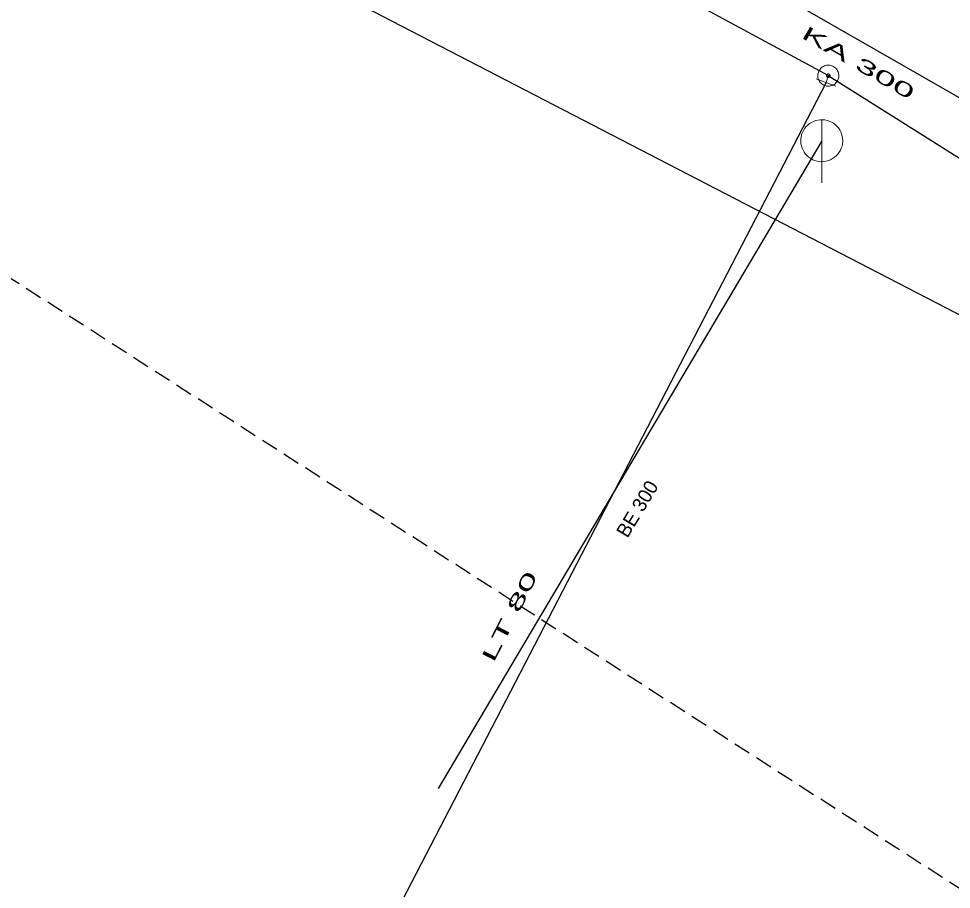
# Model space of a CAD drawing. Extents: x -687593 to -687108, y -975254 to -974717.
# Drawn here: x -687397.23 to -687352.84, y -974990.14 to -974948.69 of the extents above; entities that cross this region are included whole.
import ezdxf
from ezdxf.enums import TextEntityAlignment as Align

# ---------------------------------------------------------------- set-up
doc = ezdxf.new("R2010")
doc.units = 0
doc.header["$LTSCALE"] = 0.27
doc.linetypes.add('MEDIUM_DASHED', pattern=[4.5, 3, -1.5])
for name, color, linetype, lineweight in [('1', 7, 'Continuous', 25), ('14', 7, 'Continuous', 13), ('17', 7, 'Continuous', 25), ('22', 7, 'Continuous', 13), ('34', 7, 'Continuous', 13), ('47', 7, 'Continuous', 13), ('63', 7, 'MEDIUM_DASHED', 25)]:
    doc.layers.add(name, color=color, linetype=linetype, lineweight=lineweight)

msp = doc.modelspace()

# ---------------------------------------------------------------- linework, layer by layer
at = {"layer": '1'}
msp.add_lwpolyline([(-687190.553, -975166.941), (-687164.86, -975177.861), (-687155.924, -975158.837), (-687125.348, -975155.541), (-687124.826, -975139.621), (-687173.065, -975131.89), (-687231.828, -975028.025), (-687222.959, -975015.464), (-687237.898, -975004.026), (-687247.4, -975009.654), (-687276.892, -974983.781), (-687453.606, -974886.044), (-687460.232, -974860.45), (-687474.874, -974858.564), (-687482.889, -974882.272), (-687502.421, -974882.802), (-687499.452, -974907.164), (-687464.42, -974904.824), (-687331.319, -974973.728), (-687252.566, -975037.916), (-687192.379, -975151.48)], close=True, dxfattribs=at)
at = {"layer": '14', "lineweight": 25}
for p, q in [((-687339.967, -974959.63), (-687373.818, -974940.214)), ((-687359.013, -974954.503), (-687377.27, -974985.346))]:
    msp.add_line(p, q, dxfattribs=at)
at = {"layer": '14'}
msp.add_line((-687358.699, -974951.407), (-687358.806, -974951.731), dxfattribs=at)
at = {"layer": '17'}
for points in [[(-687358.699, -974951.407), (-687368.317, -974946.193), (-687385.348, -974936.838), (-687396.817, -974929.825)], [(-687358.699, -974951.407), (-687333.097, -974967.52), (-687321.645, -974974.737), (-687306.885, -974986.7), (-687303.706, -974988.972)], [(-687358.806, -974951.731), (-687385.932, -975004.085), (-687386.063, -975007.526), (-687384.796, -975013.772), (-687383.147, -975018.998), (-687376.673, -975029.833), (-687378.204, -975039.264)]]:
    msp.add_lwpolyline(points, dxfattribs=at)
at = {"layer": '22'}
msp.add_line((-687359.013, -974956.503), (-687359.012, -974953.503), dxfattribs=at)
msp.add_lwpolyline([(-687358.013, -974954.503), (-687358.018, -974954.394), (-687358.036, -974954.286), (-687358.066, -974954.18), (-687358.106, -974954.079), (-687358.158, -974953.982), (-687358.22, -974953.892), (-687358.292, -974953.809), (-687358.372, -974953.735), (-687358.46, -974953.669), (-687358.554, -974953.614), (-687358.654, -974953.569), (-687358.759, -974953.536), (-687358.866, -974953.514), (-687358.975, -974953.504), (-687359.085, -974953.506), (-687359.193, -974953.52), (-687359.3, -974953.545), (-687359.403, -974953.582), (-687359.501, -974953.631), (-687359.593, -974953.689), (-687359.679, -974953.758), (-687359.756, -974953.835), (-687359.825, -974953.921), (-687359.884, -974954.013), (-687359.932, -974954.111), (-687359.969, -974954.214), (-687359.995, -974954.321), (-687360.009, -974954.429), (-687360.012, -974954.539), (-687360.002, -974954.648), (-687359.981, -974954.755), (-687359.947, -974954.859), (-687359.903, -974954.959), (-687359.848, -974955.054), (-687359.782, -974955.142), (-687359.708, -974955.222), (-687359.625, -974955.294), (-687359.535, -974955.356), (-687359.439, -974955.408), (-687359.337, -974955.449), (-687359.232, -974955.479), (-687359.124, -974955.497), (-687359.014, -974955.503), (-687358.905, -974955.497), (-687358.797, -974955.479), (-687358.692, -974955.45), (-687358.59, -974955.409), (-687358.493, -974955.357), (-687358.403, -974955.295), (-687358.32, -974955.224), (-687358.245, -974955.144), (-687358.18, -974955.056), (-687358.124, -974954.962), (-687358.08, -974954.862), (-687358.046, -974954.758), (-687358.024, -974954.65), (-687358.014, -974954.541)], close=True, dxfattribs=at)
at = {"layer": '34'}
msp.add_line((-687359.273, -974951.552), (-687358.339, -974951.91), dxfattribs=at)
at = {"layer": '47'}
for points in [[(-687358.275, -974951.673), (-687358.25, -974951.627), (-687358.229, -974951.579), (-687358.214, -974951.529), (-687358.204, -974951.478), (-687358.199, -974951.425), (-687358.2, -974951.373), (-687358.207, -974951.321), (-687358.218, -974951.27), (-687358.235, -974951.221), (-687358.256, -974951.173), (-687358.283, -974951.128), (-687358.315, -974951.086), (-687358.35, -974951.048), (-687358.39, -974951.014), (-687358.432, -974950.983), (-687358.478, -974950.958), (-687358.526, -974950.937), (-687358.577, -974950.922), (-687358.627, -974950.912), (-687358.68, -974950.907), (-687358.732, -974950.908), (-687358.785, -974950.914), (-687358.836, -974950.926), (-687358.885, -974950.942), (-687358.932, -974950.964), (-687358.977, -974950.991), (-687359.019, -974951.023), (-687359.057, -974951.058), (-687359.091, -974951.098), (-687359.122, -974951.14), (-687359.147, -974951.186), (-687359.168, -974951.234), (-687359.184, -974951.284), (-687359.193, -974951.335), (-687359.198, -974951.388), (-687359.198, -974951.44), (-687359.192, -974951.492), (-687359.18, -974951.543), (-687359.163, -974951.593), (-687359.141, -974951.64), (-687359.114, -974951.685), (-687359.083, -974951.727), (-687359.047, -974951.765), (-687359.007, -974951.799), (-687358.965, -974951.83), (-687358.919, -974951.855), (-687358.871, -974951.876), (-687358.822, -974951.891), (-687358.77, -974951.901), (-687358.717, -974951.906), (-687358.665, -974951.906), (-687358.614, -974951.899), (-687358.563, -974951.888), (-687358.513, -974951.87), (-687358.465, -974951.849), (-687358.42, -974951.822), (-687358.379, -974951.791), (-687358.34, -974951.755), (-687358.306, -974951.715)], [(-687358.629, -974951.45), (-687358.624, -974951.443), (-687358.622, -974951.435), (-687358.619, -974951.427), (-687358.617, -974951.419), (-687358.617, -974951.41), (-687358.617, -974951.401), (-687358.618, -974951.392), (-687358.619, -974951.384), (-687358.623, -974951.376), (-687358.626, -974951.368), (-687358.631, -974951.361), (-687358.636, -974951.354), (-687358.642, -974951.348), (-687358.647, -974951.342), (-687358.655, -974951.337), (-687358.662, -974951.332), (-687358.67, -974951.33), (-687358.678, -974951.327), (-687358.686, -974951.325), (-687358.695, -974951.325), (-687358.704, -974951.325), (-687358.713, -974951.326), (-687358.721, -974951.327), (-687358.73, -974951.33), (-687358.737, -974951.334), (-687358.744, -974951.339), (-687358.751, -974951.344), (-687358.757, -974951.35), (-687358.763, -974951.355), (-687358.768, -974951.363), (-687358.773, -974951.37), (-687358.775, -974951.378), (-687358.778, -974951.386), (-687358.78, -974951.394), (-687358.78, -974951.403), (-687358.781, -974951.411), (-687358.779, -974951.421), (-687358.778, -974951.429), (-687358.775, -974951.438), (-687358.771, -974951.445), (-687358.766, -974951.452), (-687358.761, -974951.459), (-687358.755, -974951.465), (-687358.75, -974951.471), (-687358.742, -974951.476), (-687358.735, -974951.481), (-687358.727, -974951.483), (-687358.719, -974951.486), (-687358.711, -974951.488), (-687358.702, -974951.488), (-687358.694, -974951.489), (-687358.684, -974951.487), (-687358.676, -974951.486), (-687358.668, -974951.482), (-687358.66, -974951.479), (-687358.653, -974951.474), (-687358.646, -974951.469), (-687358.64, -974951.463), (-687358.634, -974951.458)]]:
    msp.add_lwpolyline(points, close=True, dxfattribs=at)
at = {"layer": '63'}
msp.add_lwpolyline([(-687526.998, -974914.677), (-687484.572, -974843.781), (-687484.572, -974843.781), (-687425.956, -974881.183), (-687425.956, -974881.183), (-687214.941, -975003.438), (-687214.941, -975003.438), (-687108.316, -975140.766), (-687108.316, -975140.766), (-687138.461, -975189.333), (-687138.461, -975189.333), (-687208.242, -975184.867), (-687208.242, -975184.867), (-687273.556, -975040.84), (-687273.556, -975040.84), (-687454.985, -974924.168), (-687454.985, -974924.168)], close=True, dxfattribs=at)

# ---------------------------------------------------------------- texts
at = {"layer": '1', "width": 2.05}
for s, rotation, p in [('KA 300', 330, (-687357.4347, -974951.0789)), ('KA 300', 330, (-687357.4347, -974951.0789)), ('KA 300', 330, (-687357.4347, -974951.0789)), ('KA 300', 330, (-687357.4347, -974951.0789)), ('KA 300', 330, (-687357.4347, -974951.0789)), ('LT 80 ', 63, (-687373.4582, -974977.0773)), ('LT 80 ', 63, (-687373.4582, -974977.0773)), ('LT 80 ', 63, (-687373.4582, -974977.0773)), ('LT 80 ', 63, (-687373.4582, -974977.0773)), ('LT 80 ', 63, (-687373.4582, -974977.0773))]:
    msp.add_text(s, height=0.6667, rotation=rotation, dxfattribs=at).set_placement(p, align=Align.CENTER)
at = {"layer": '1'}
msp.add_text('BE 300', height=0.6667, rotation=59, dxfattribs=at).set_placement((-687367.505, -974972.2021), align=Align.CENTER)
msp.add_text('BE 300', height=0.6667, rotation=59, dxfattribs=at).set_placement((-687367.505, -974972.2021), align=Align.CENTER)
msp.add_text('BE 300', height=0.6667, rotation=59, dxfattribs=at).set_placement((-687367.505, -974972.2021), align=Align.CENTER)
msp.add_text('BE 300', height=0.6667, rotation=59, dxfattribs=at).set_placement((-687367.505, -974972.2021), align=Align.CENTER)
msp.add_text('BE 300', height=0.6667, rotation=59, dxfattribs=at).set_placement((-687367.505, -974972.2021), align=Align.CENTER)

doc.saveas('drawing.dxf')
